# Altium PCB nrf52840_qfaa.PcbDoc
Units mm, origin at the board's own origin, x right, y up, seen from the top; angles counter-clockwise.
Board outline 16 x 13.5 mm, 2 copper layers (Top Layer, Bottom Layer), stack 1.671 mm thick; 23 components, 44 nets, 95 pads, 62 vias.
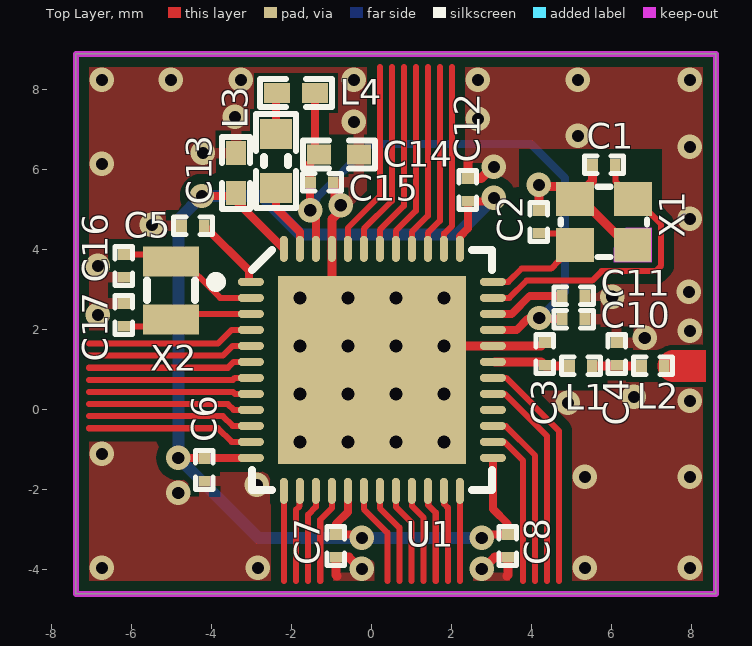
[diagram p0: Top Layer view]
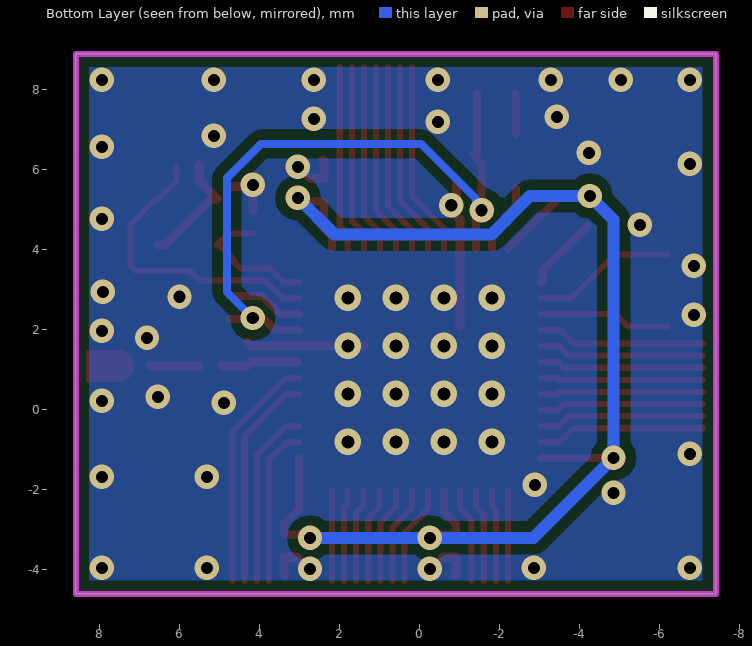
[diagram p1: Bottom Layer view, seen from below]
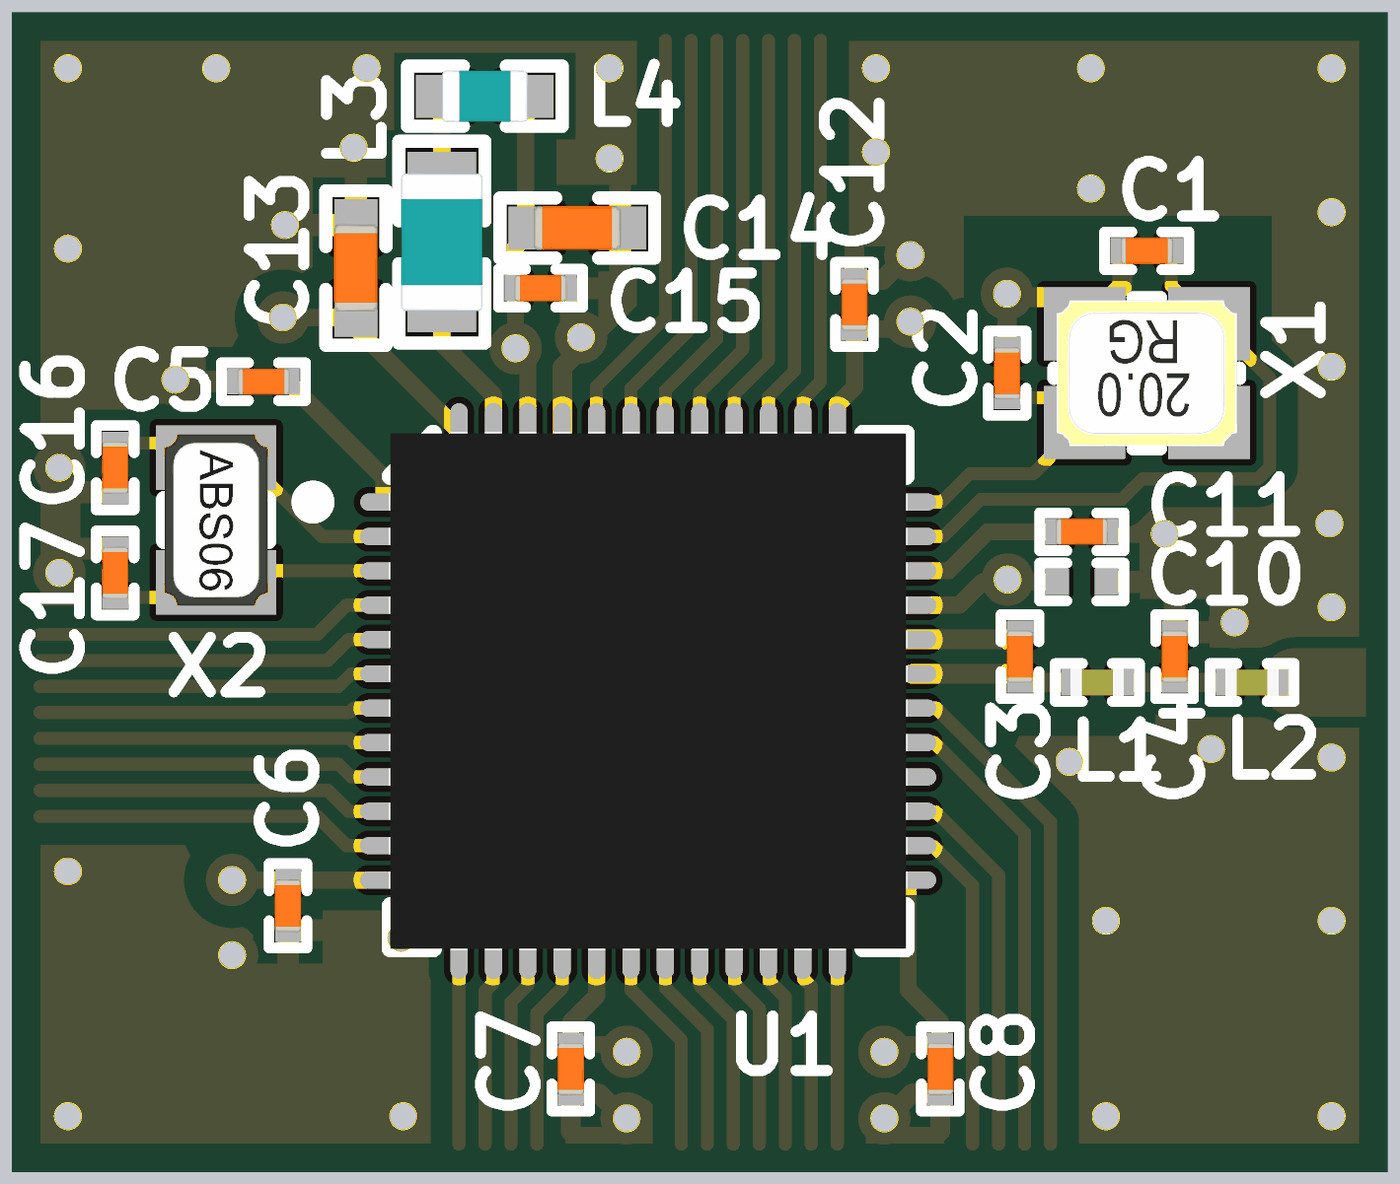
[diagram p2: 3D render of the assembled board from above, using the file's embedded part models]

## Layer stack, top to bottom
Top Solder: solder mask 0.0102, Solder Resist, Dk 3.5
Top Layer: signal copper 0.0356
Dielectric1: core 1.6002, FR-4, Dk 4.8
Bottom Layer: signal copper 0.0356
Bottom Solder: solder mask 0.0102, Solder Resist, Dk 3.5

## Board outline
-7.4,-4.6 8.6,-4.6 8.6,8.9 -7.4,8.9

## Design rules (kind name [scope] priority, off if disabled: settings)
Clearance Polygon_ANT [(InNamedPolygon('Top_Layer-GND')) or (InNamedPolygon('Bottom_Layer-GND')) vs InNet('RF')] p1: gap=0.127 ignorepadtopadclearanceinfootprint=FALSE except(0: Arc-Hole Track-Hole SMDPad-Hole THPad-Hole Via-Hole Fill-Hole Poly-Hole Region-Hole Text-Hole)
Clearance Polygon [(InNamedPolygon('Top_Layer-GND')) or (InNamedPolygon('Bottom_Layer-GND'))] p2: gap=0.254 ignorepadtopadclearanceinfootprint=FALSE except(0: Arc-Hole Track-Hole SMDPad-Hole THPad-Hole Via-Hole Fill-Hole Poly-Hole Region-Hole Text-Hole)
Clearance [All] p3: gap=0.15 ignorepadtopadclearanceinfootprint=FALSE
ComponentClearance [All] p1 off: gap=0.254 collisioncheckmode=3 verticalgap=0.254 showdistances=FALSE
FabricationTestPointUsage TestPointUsage [All] p1: valid=0 allowmultiple=FALSE
FabricationTestpoint Testpoint [All] p1: side=3 testpointundercomponent=TRUE minsize=1.016 maxsize=2.54 preferedsize=1.524 minholesize=0 maxholesize=1.016 preferedholesize=0.813 testpointgrid=0.025 allowsidetop=TRUE allowsidebottom=TRUE usegrid=TRUE gridtolerance=0
Height [All] p1 off: minheight=0 maxheight=25.4 prefheight=12.7
HoleSize [All] p1: absolutevalues=TRUE maxlimit=4.064 minlimit=0.305 maxpercent=80.000 minpercent=20.000
MinimumAnnularRing [All] p1 off: minimumring=0.152
PolygonConnect PolygonConnect_1 [isVia and innet(gnd)] p1: connectstyle=Direct reliefconductorwidth=0.254 reliefentries=4 polygonreliefangle="90 Angle" airgapwidth=0.254
PolygonConnect [All] p2: connectstyle=Relief reliefconductorwidth=0.254 reliefentries=4 polygonreliefangle="90 Angle" airgapwidth=0.254
RoutingVias [All] p1: holewidth=0.406 width=0.813 viastyle="Through Hole" minholewidth=0.254 minwidth=0.254 maxholewidth=0.711 maxwidth=1.27
SilkToSolderMaskClearance SilkscreenOverComponentPads [IsPad] p1: minsilkscreentomaskgap=0.254 clearancetoexposedcopper=TRUE
SolderMaskExpansion SolderMaskExpansion_via [IsVia] p1: expansion=0.102 istentingtop=TRUE
SolderMaskExpansion [All] p2: expansion=0.076 istentingtop=FALSE
Width [All] p1: maxlimit=2.54 minlimit=0.15 preferedwidth=0.15
24 further rules are at their usual default settings.

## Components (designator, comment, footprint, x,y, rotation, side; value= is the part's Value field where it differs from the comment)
C1 "12pF" CAPC0603X03L_C#1 5.8,6.125 r180 top
C2 "12pF" CAPC0603X03L_C#1 4.175,4.7 r90 top
C3 "1.0pF" CAPC0603X03L_C#1 4.325,1.4 r270 top
C4 "1.2pF" CAPC0603X03L_C#1 6.125,1.4 r270 top
C5 "100nF" CAPC0603X03L_C#2 -4.475,4.601 r180 top
C6 "100nF" CAPC0603X03L_C#2 -4.19,-1.5 r270 top
C7 "100nF" CAPC0603X03L_C#2 -0.9,-3.4 r270 top
C8 "100nF" CAPC0603X03L_C#2 3.398,-3.4 r270 top
C10 "N.C." CAPC0603X03L_C_NC 5.045,2.27 r180 top
C11 "100pF" CAPC0603X03L_C#1 5.045,2.854 r0 top
C12 "100nF" CAPC0603X03L_C#2 2.4,5.5 r90 top
C13 "1.0µF" CAPC1005X04L -3.4,5.925 r90 top
C14 "1.0µF" CAPC1005X04L -0.825,6.39 r180 top
C15 "47nF" CAPC0603X03L_C#1 -1.251,5.69 r0 top
C16 "12pF" CAPC0603X03L_C#2 -6.2,3.6 r270 top
C17 "12pF" CAPC0603X03L_C#2 -6.2,2.375 r90 top
L1 "4.7nH" INDC0603X03L_C 5.225,1.1 r0 top
L2 "2.2nH" INDC0603X03L_C 7.025,1.1 r0 top
L3 "10µH" INDC1608X06L -2.4,6.225 r270 top
L4 "15nH" INDC1005X04L -1.9,7.925 r180 top
U1 "nRF52840-QFAA" QFN40P600X600X90-48N 0,1 r0 top locked
X1 "32MHz" XTAL_2016_NT 5.8,4.7 r180 top
X2 "32.768kHz" XTAL_2012 -5.025,2.99 r270 top

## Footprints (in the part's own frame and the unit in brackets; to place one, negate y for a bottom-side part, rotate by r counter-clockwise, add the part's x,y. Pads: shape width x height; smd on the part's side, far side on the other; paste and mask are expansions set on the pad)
CAPC0603X03L_C#1 [mm] "Chip Capacitor, 2-Leads, Body 0.6x0.3mm, IPC High Density"
  rect 0.27x0.3 smd: 1(-0.285,0) 2(0.285,0)
  silkscreen extent -0.49,-0.22 0.49,0.22, body extent -0.3,-0.15 0.31,0.15, height 0.3
CAPC0603X03L_C#2 [mm] "Chip Capacitor, 2-Leads, Body 0.6x0.3mm, IPC High Density"
  rect 0.27x0.3 smd mask+0.05: 1(-0.285,0) 2(0.285,0)
  silkscreen extent -0.49,-0.22 0.49,0.22, body extent -0.3,-0.15 0.31,0.15, height 0.3
CAPC0603X03L_C_NC [mm] "Chip Capacitor, 2-Leads, Body 0.6x0.3mm, IPC High Density"
  rect 0.27x0.3 smd mask+0.05: 1(-0.285,0) 2(0.285,0)
  silkscreen extent -0.49,-0.22 0.49,0.22
CAPC1005X04L [mm] "Chip Capacitor, 2-Leads, Body 1.0x0.5mm, IPC High Density"
  rect 0.6x0.5 smd: 1(-0.5,0) 2(0.5,0)
  silkscreen extent -0.9,-0.35 0.9,0.35, body extent -0.51,-0.25 0.51,0.25, height 0.5
INDC0603X03L_C [mm] "Chip Inductor, 2-Leads, Body 0.6x0.3mm, IPC High Density"
  rect 0.27x0.3 smd: 1(-0.285,0) 2(0.285,0)
  silkscreen extent -0.49,-0.22 0.49,0.22, body extent -0.31,-0.16 0.31,0.16, height 0.26
INDC1005X04L [mm] "Chip Inductor, 2-Leads, Body 1.0x0.5mm, IPC High Density"
  rect 0.65x0.5 smd: 1(-0.475,0) 2(0.475,0)
  silkscreen extent -0.9,-0.35 0.9,0.35, body extent -0.5,-0.3 0.5,0.3, height 0.5
INDC1608X06L [mm] "Chip Inductor, 2-Leads, Body 1.6x0.8mm, IPC High Density"
  rect 0.75x0.8 smd: 1(-0.675,0) 2(0.675,0)
  silkscreen extent -1.17,-0.5 1.17,0.5, body extent -0.8,-0.48 0.8,0.48, height 0.8
QFN40P600X600X90-48N [mm] "QFN, 48-Leads, Body 6,0x6,0mm (max), Pitch 0,40mm, IPC Medium Density"
  oval 0.65x0.2 smd: 1(-3.025,2.2) 2(-3.025,1.8) 3(-3.025,1.4) 4(-3.025,1) 5(-3.025,0.6) 6(-3.025,0.2) 7(-3.025,-0.2) 8(-3.025,-0.6) 9(-3.025,-1) 10(-3.025,-1.4) 11(-3.025,-1.8) 12(-3.025,-2.2) 25(3.025,-2.2) 26(3.025,-1.8) 27(3.025,-1.4) 28(3.025,-1) 29(3.025,-0.6) 30(3.025,-0.2) 31(3.025,0.2) 32(3.025,0.6) 33(3.025,1) 34(3.025,1.4) 35(3.025,1.8) 36(3.025,2.2)
  oval 0.2x0.65 smd: 13(-2.2,-3.025) 14(-1.8,-3.025) 15(-1.4,-3.025) 16(-1,-3.025) 17(-0.6,-3.025) 18(-0.2,-3.025) 19(0.2,-3.025) 20(0.6,-3.025) 21(1,-3.025) 22(1.4,-3.025) 23(1.8,-3.025) 24(2.2,-3.025) 37(2.2,3.025) 38(1.8,3.025) 39(1.4,3.025) 40(1,3.025) 41(0.6,3.025) 42(0.2,3.025) 43(-0.2,3.025) 44(-0.6,3.025) 45(-1,3.025) 46(-1.4,3.025) 47(-1.8,3.025) 48(-2.2,3.025)
  rect 4.7x4.7 smd: 49(0,0)
  silkscreen extent -4.02,-3 3,3, body extent -3.02,-3.02 3.02,3.02, height 0.86
XTAL_2012 [mm] "XTAL SMD 2.0 x 1.2 mm"
  rect 0.75x1.4 smd: 1(-0.725,0) 2(0.725,0)
  silkscreen extent -0.24,-0.6 0.24,0.6, body extent -1,-0.61 1,0.61, height 0.6
XTAL_2016_NT [mm] "Crystal 2.0 x 1.6 mm"
  rect 0.95x0.85 smd: 1(-0.725,-0.575) 2(-0.725,0.575) 2(0.725,-0.575) 3(0.725,0.575)
  Top Layer lines w0.225: 0.725,-0.575 0.575,-0.575 -0.575,0.575 -0.725,0.575
  Top Layer keep-out lines w0.01: -0.25,0.65 -0.25,1 -1.2,1 -1.2,0.15 -0.55,0.15
  silkscreen extent -1.08,-0.88 1.08,0.88, body extent -1.05,-0.85 1.05,0.85, height 0.56

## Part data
C1 C2 C16 C17: library part C0201-12p, "Capacitor, NP0, ±2%"
C3: library part C0201-1.0p, "Capacitor, NP0, ±10%"
C4: library part C0201-1.2p, "Capacitor, NP0, ±10%"
C5 C6 C7 C8 C12: library part C0201-100n, "Capacitor, X5R, ±10%"
C10: library part C0201-N.C., "Not mounted"
C11: library part C0201-100p, "Capacitor, NP0, ±5%"
C13 C14: library part C0402-1µ0, "Capacitor, X5R, ±10%"
C15: library part C0201-47n, "Capacitor, X5R, ±10%"
L1: library part L0201-4n7, "High frequency chip inductor ±5%"
L2: library part L0201-2n2, "High frequency chip inductor ±5%"
L3: library part L0603-10µ-TDK, "Chip inductor, IDC,min = 50 mA, ±20%"
L4: library part L0402-15n, "High frequency chip inductor ±10%"
U1: "Multi-protocol Bluetooth Low Energy, IEEE 802.15.4, ANT and 2.4GHz proprietary system-on-chip"
X1: library part XTAL_SMD2016_32MHz_8pF_General_NT, "XTAL SMD 2016, 32MHz, Cl=8pF, Total Tol: ±30ppm"
X2: library part XTAL_SMD2012_32.768kHz_9pF_General, "XTAL SMD 2012, 32.768kHz, Cl=9pF, Total Tol: ±50ppm"

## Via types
v1: diameter 0.61, hole 0.305, Top Layer to Bottom Layer, tented both sides, 46 vias
v2: diameter 0.66, hole 0.33, Top Layer to Bottom Layer, tented both sides, 16 vias

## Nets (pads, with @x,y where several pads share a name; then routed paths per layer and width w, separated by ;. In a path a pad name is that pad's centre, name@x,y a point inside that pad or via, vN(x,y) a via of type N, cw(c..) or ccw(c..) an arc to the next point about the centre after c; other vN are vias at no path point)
DEC1: C5.1 U1.1 | length 1.9
  Top Layer w0.2: C5.1 -4.19,4.586 -4.155,4.551 -4.14,4.551 -3.071,3.483 -3.071,3.2 U1.1
DEC3: C11.1 U1.34 | length 1.9
  Top Layer w0.2: U1.34 3.493,2.4 3.946,2.853 C11.1@4.74,2.853
DEC4_6: C10.2 C14.2 C15.1 L4.1 U1.33 U1.46 | length 17.1
  Top Layer w0.2: v1(-1.543,4.991) -1.543,6.172 C14.2 ; C14.2@-1.425,6.39 L4.1 L4.1@-1.4,7.9 ; U1.46 v1@-1.4,4.94 ; U1.33 3.62,2 3.89,2.27 C10.2
  Bottom Layer w0.2: v1(-1.543,4.991) -1.543,5.101 -1.39,5.254 -1.39,5.293 -0.033,6.65 3.975,6.65 4.825,5.8 4.825,2.942 v1(4.181,2.298)
GND: C1.2 C2.2 C3.1 C4.1 C5.2 C6.2 C7.2 C8.2 C10.1 C11.2 C12.2 C13.2 C14.1 C15.2 C16.2 C17.2 U1.32 U1.45 U1.49 X1.2 | length 12.8
  Top Layer w0.229: U1.49@-1,2.095 U1.45 -1,4.766 -0.775,4.991 v1@-0.775,5.275 ; C15.2@-0.915,5.69 -0.915,5.226 v1@-0.781,5.092 ; -0.875,-4.15 -0.9,-4.125 C7.2 -0.574,-3.685 -0.284,-3.975 v1(-0.25,-3.975) ; U1.49@1.4,1.6 4.231,1.6 C3.1@4.316,1.685 ; 2.425,6.25 2.4,6.225 C12.2 2.726,5.785 3.016,6.075 v1(3.05,6.075) ; v1(2.748,-3.975) 2.782,-3.975 3.072,-3.685 C8.2 3.398,-4.125 3.373,-4.15 ; C2.2 v1(4.175,5.625) ; v1@4.214,5.586 X1.2@4.764,5.586 ; X1.2@5.075,5.275 5.515,5.715 C1.2
  other v1: -6.75,-3.95 -2.85,-3.95 5.325,-3.95 7.95,-3.95 -4.84,-2.075 -2.875,-1.875 5.325,-1.675 7.95,-1.675 -6.75,-1.1 4.9,0.175 7.95,0.225 6.55,0.325 6.823,1.8 7.95,1.975 -6.85,2.375 6.01,2.829 7.925,2.95 -6.85,3.6 -5.5,4.625 7.95,4.775 -0.781,5.117 -6.75,6.15 -4.225,6.425 7.95,6.575 5.15,6.85 -0.45,7.2 2.65,7.275 -3.425,7.325 -6.75,8.25 -5.025,8.25 -3.275,8.25 -0.45,8.25 2.65,8.25 5.15,8.25 7.95,8.25
  other v2: -1.8,-0.8 -0.6,-0.8 0.6,-0.8 1.8,-0.8 -1.8,0.4 -0.6,0.4 0.6,0.4 1.8,0.4 -1.8,1.6 -0.6,1.6 0.6,1.6 1.8,1.6 -1.8,2.8 -0.6,2.8 0.6,2.8 1.8,2.8
NetC3_2: C3.2 L1.1 U1.31 | length 1.9
  Top Layer w0.229: U1.31@3.075,1.2 4.231,1.2 4.316,1.115 4.331,1.1 L1.1
NetC4_2: C4.2 L1.2 L2.1 | length 1.2
  Top Layer w0.229: L1.2 L2.1
NetL3_1: L3.1 L4.2 | length 1
  Top Layer w0.2: L3.1 -2.4,7.9 L4.2
NetL3_2: L3.2 U1.47 | length 1.8
  Top Layer w0.2: L3.2 -2.4,5.045 -1.8,4.445 U1.47
P0.00/XL1: C16.1 U1.2 X2.1 | length 3.6
  Top Layer w0.152: C16.1 -4.88,3.885 -3.795,2.8 U1.2
P0.01/XL2: C17.1 U1.3 X2.2 | length 3.3
  Top Layer w0.152: C17.1 -5.2,2.09 X2.2 -4.89,2.4 U1.3
P0.02/AIN0: U1.40 | length 4.7
  Top Layer w0.15: U1.40 1,4.452 1.4,4.852 1.4,8.575
P0.03/AIN1: U1.39 | length 4.7
  Top Layer w0.152: U1.39 1.4,4.426 1.701,4.727 1.701,8.575
P0.04/AIN2: U1.4 | length 4.2
  Top Layer w0.152: -7.075,1.658 -3.851,1.658 -3.509,2 U1.4
P0.05/AIN3: U1.5 | length 4.2
  Top Layer w0.152: -7.075,1.356 -3.726,1.356 -3.482,1.6 U1.5
P0.07: U1.6 | length 4.1
  Top Layer w0.152: -7.075,1.054 -3.6,1.054 -3.454,1.2 U1.6
P0.08: U1.7 | length 4.1
  Top Layer w0.152: -7.075,0.751 -3.475,0.751 -3.426,0.8 U1.7
P0.09/NFC1: U1.29 | length 5.4
  Top Layer w0.152: U1.29 3.325,0.4 4.379,-0.654 4.379,-4.275
P0.10/NFC2: U1.30 | length 6
  Top Layer w0.152: U1.30 3.353,0.8 4.682,-0.529 4.682,-4.275
P0.11: U1.10 | length 4.2
  Top Layer w0.152: -7.075,-0.156 -3.726,-0.156 -3.482,-0.4 U1.10
P0.12: U1.11 | length 4.2
  Top Layer w0.152: -7.075,-0.458 -3.851,-0.458 -3.509,-0.8 U1.11
P0.13: U1.13 | length 2.3
  Top Layer w0.152: -2.2,-4.275 U1.13
P0.14: U1.14 | length 2.3
  Top Layer w0.152: -1.898,-4.275 -1.898,-2.496 -1.806,-2.404 -1.806,-2.031 U1.14
P0.17: U1.15 | length 2.3
  Top Layer w0.152: -1.595,-4.275 -1.595,-2.621 -1.4,-2.426 U1.15
P0.18/RESET: U1.16 | length 2.4
  Top Layer w0.152: -1.293,-4.275 -1.293,-2.747 -1,-2.454 U1.16
P0.19: U1.18 | length 2.5
  Top Layer w0.152: U1.18 -0.2,-2.482 0.386,-3.067 0.386,-4.275
P0.20: U1.19 | length 2.5
  Top Layer w0.152: U1.19 0.2,-2.454 0.688,-2.942 0.688,-4.275
P0.21: U1.20 | length 2.4
  Top Layer w0.152: U1.20 0.6,-2.426 0.99,-2.817 0.99,-4.275
P0.22: U1.21 | length 2.4
  Top Layer w0.152: U1.21 1.006,-2.031 1.006,-2.404 1.293,-2.691 1.293,-4.275
P0.23: U1.22 | length 2.3
  Top Layer w0.152: U1.22 1.409,-2.034 1.409,-2.38 1.595,-2.566 1.595,-4.275
P0.24: U1.23 | length 2.3
  Top Layer w0.152: U1.23 1.809,-2.034 1.809,-2.352 1.898,-2.441 1.898,-4.275
P0.28/AIN4: U1.41 | length 4.8
  Top Layer w0.15: U1.41 0.6,4.476 1.1,4.976 1.1,8.575
P0.29/AIN5: U1.42 | length 4.8
  Top Layer w0.15: U1.42 0.2,4.5 0.8,5.1 0.8,8.575
P0.30/AIN6: U1.43 | length 4.8
  Top Layer w0.15: U1.43 -0.2,4.525 0.5,5.224 0.5,8.575
P0.31/AIN7: U1.44 | length 4.9
  Top Layer w0.15: U1.44 -0.6,4.549 0.2,5.349 0.2,8.575
P1.00: U1.24 | length 2.3
  Top Layer w0.152: 2.2,-4.275 U1.24
P1.08: U1.8 | length 4.1
  Top Layer w0.152: -7.075,0.449 -3.475,0.449 -3.426,0.4 U1.8
P1.09: U1.9 | length 4.1
  Top Layer w0.152: -7.075,0.146 -3.6,0.146 -3.454,0 U1.9
P1.15: U1.38 | length 4.6
  Top Layer w0.152: U1.38 1.806,4.031 1.806,4.404 2.003,4.601 2.003,8.575
RF: L2.2 | length 0.4
  Top Layer w0.8: 7.535,1.1 7.95,1.1
SWDCLK: U1.27 | length 4.5
  Top Layer w0.152: U1.27 3.034,-0.409 3.348,-0.409 4.077,-1.138 4.077,-4.275
SWDIO: U1.26 | length 4
  Top Layer w0.152: U1.26 3.034,-0.809 3.32,-0.809 3.774,-1.263 3.774,-4.275
VDD_NRF: C6.1 C7.1 C8.1 C12.1 C13.1 U1.12 U1.17 U1.25 U1.37 U1.48 | length 33.9
  Top Layer w0.2: v1@-4.63,-1.2 U1.12 ; v1(-4.25,5.349) -3.524,5.349 U1.48 ; U1.17 -0.6,-2.55 -0.898,-2.848 -0.898,-3.112 C7.1 v1@-0.438,-3.115 ; U1.37 2.2,4.337 2.403,4.54 2.403,5.212 C12.1 2.862,5.215 2.947,5.3 v1(3.05,5.3) ; v1(2.748,-3.2) 2.851,-3.2 2.936,-3.115 C8.1 3.395,-3.112 3.395,-2.848 3.025,-2.477 U1.25
  Bottom Layer w0.3: v1(2.748,-3.2) -2.84,-3.2 v1(-4.84,-1.2) -4.84,4.758 v1(-4.25,5.349) -2.749,5.349 -2.148,4.748 -2.148,4.74 -1.794,4.386 2.136,4.386 v1(3.05,5.3)
  other v1: -0.25,-3.2
XC1: C1.1 U1.35 X1.1 | length 7.6
  Top Layer w0.15: U1.35 3.434,2.8 3.864,3.23 5.505,3.23 5.745,3.47 7.095,3.47 7.23,3.605 7.23,4.645 6.6,5.275 X1.1 6.085,5.715 C1.1
XC2: C2.1 U1.36 X1.3 | length 3.5
  Top Layer w0.15: U1.36 3.41,3.2 3.74,3.53 4.48,3.53 4.675,3.725 4.675,3.775 5.025,4.125 X1.3 4.785,4.415 C2.1
pads on no net: U1.28

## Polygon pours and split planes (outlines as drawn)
GND on Bottom Layer "Bottom_Layer-GND" (solid, remove dead copper, pour order 1001): -9.474,10.16 -9.474,-6.761 10.008,-6.761 10.008,10.16 -9.474,10.16
GND on Top Layer "Top_Layer-GND" (solid, remove dead copper, pour order 1000): -8.966,10.414 -8.966,-6.761 9.22,-6.761 9.22,10.414 -8.966,10.414

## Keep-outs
Keep-Out Layer:
  the board outline again, w0.152

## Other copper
Top Layer:
  rectangle net RF: 7.825,0.7 8.35,1.5
  pour cut-out: 7.254,6.529 3.675,6.529 3.675,3.275 7.254,3.275
  pour cut-out: 4.125,1.991 5.8,1.991 5.8,1.525 5.9,1.525 5.9,0.475 4.125,0.475

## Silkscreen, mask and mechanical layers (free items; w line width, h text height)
Mechanical 1:
  the board outline again, w0.152

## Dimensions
8.6,8.9 to 8.6,-4.6 on Mechanical 3
-7.4,-4.6 to 8.6,-4.6 on Mechanical 3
